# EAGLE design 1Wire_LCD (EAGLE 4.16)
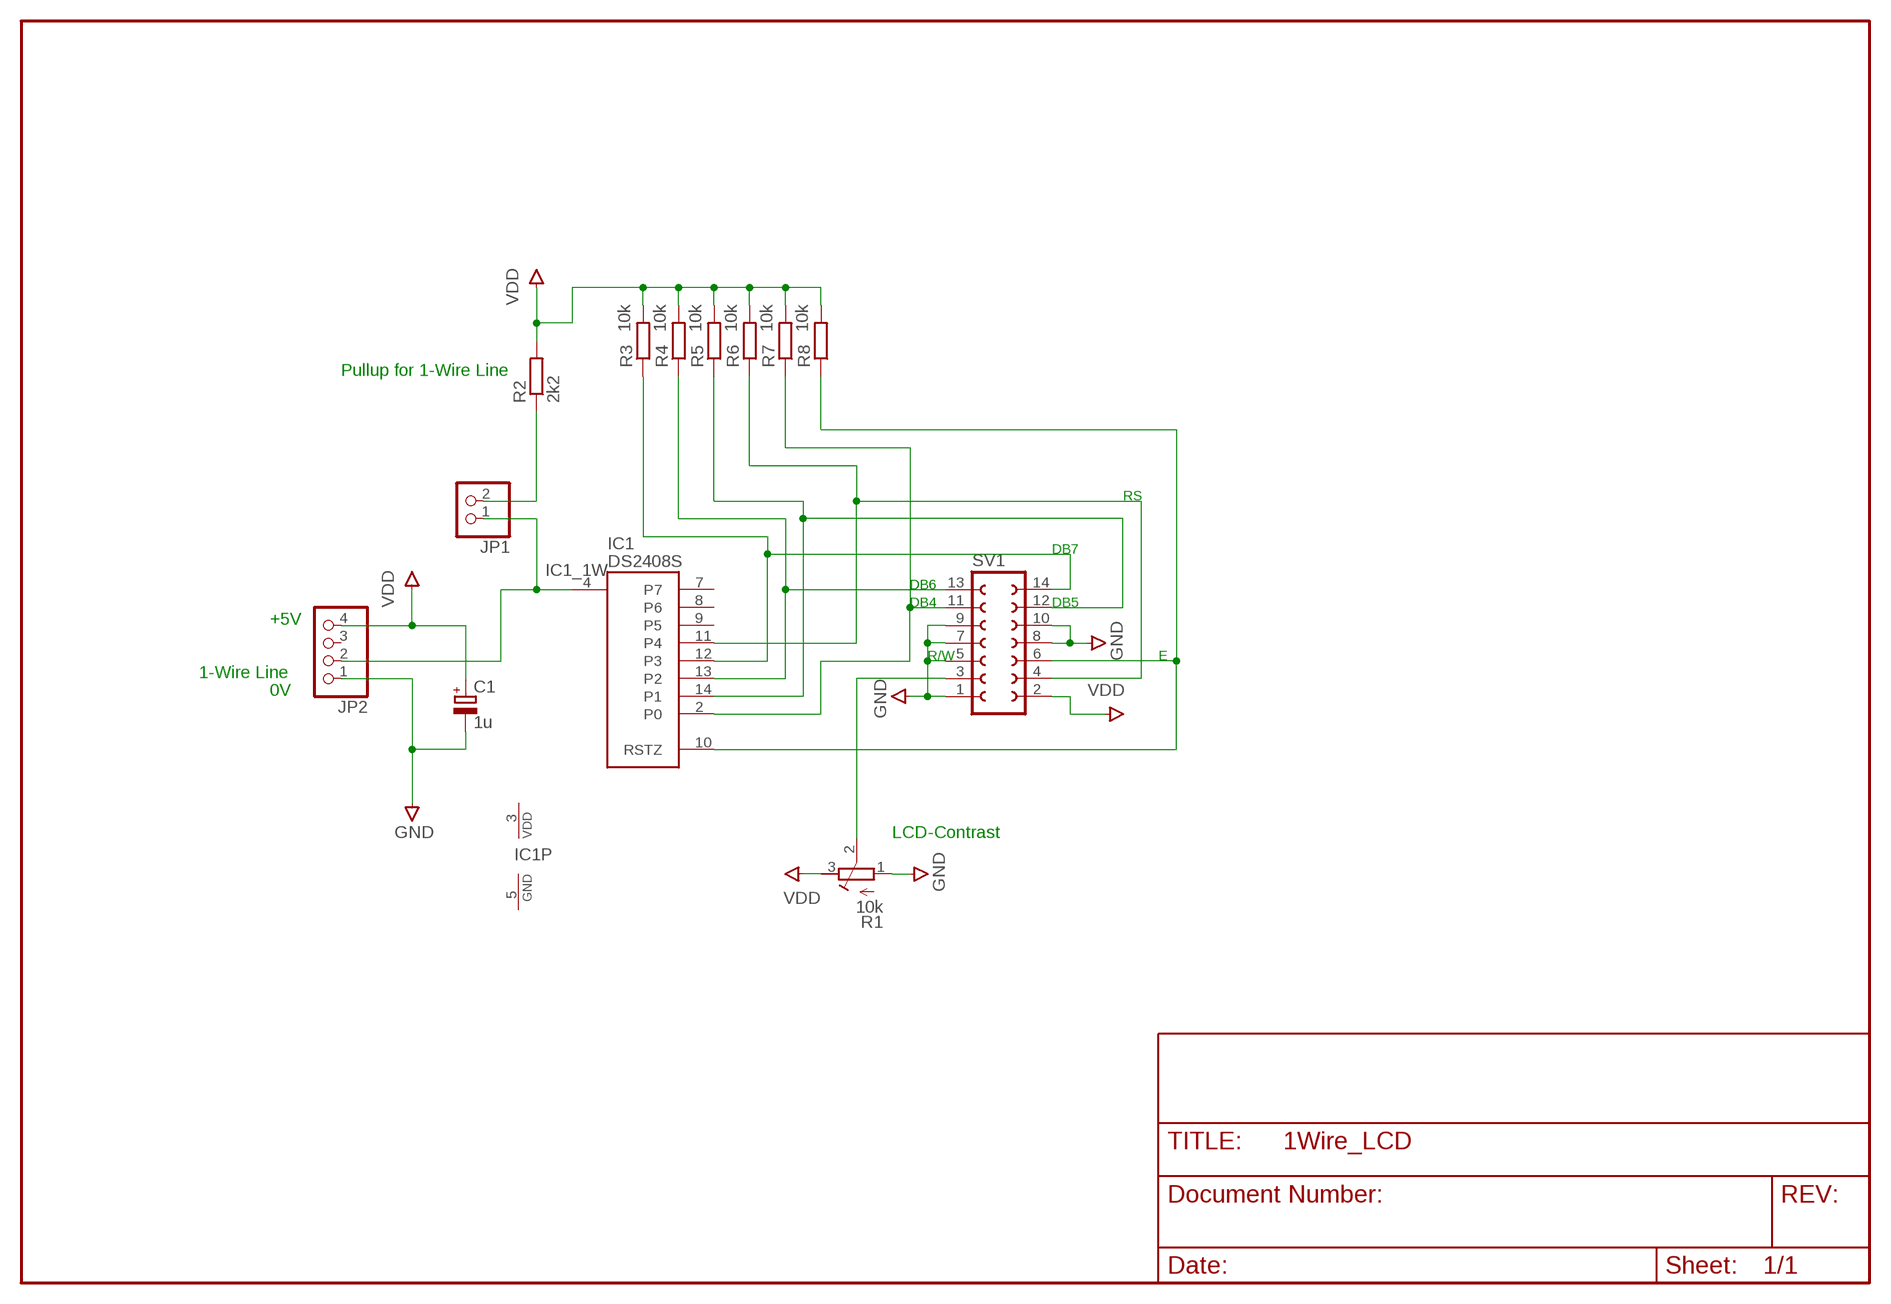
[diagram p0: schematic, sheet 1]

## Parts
C1  1u  CPOL-EUSMCP  [SMC_P]
IC1  DS2408S  [SO16]
JP1  PINHD-1X2  [1X02]
JP2  PINHD-1X4  [1X04]
R1  10k  R-TRIMM4G/J  [RTRIM4G/J]
R2  2k2  R-EU_M1206  [M1206]
R3  10k  R-EU_M1206  [M1206]
R4  10k  R-EU_M1206  [M1206]
R5  10k  R-EU_M1206  [M1206]
R6  10k  R-EU_M1206  [M1206]
R7  10k  R-EU_M1206  [M1206]
R8  10k  R-EU_M1206  [M1206]
SV1  FE07-2  [FE07-2]

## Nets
CONTRAST: R1.2(S) SV1.3
DB4: IC1.2(P0) R7.1 SV1.11
DB5: IC1.14(P1) R5.1 SV1.12
DB6: IC1.13(P2) R4.1 SV1.13
DB7: IC1.12(P3) R3.1 SV1.14
E: IC1.10(RSTZ) R8.1 SV1.6
GND: C1.- JP2.1 R1.1(E) SV1.1 SV1.5 SV1.7 SV1.8 SV1.9 SV1.10
I/O: IC1.4(1W) JP1.1 JP2.2
N$2: JP1.2 R2.1
RS: IC1.11(P4) R6.1 SV1.4
VDD: C1.+ JP2.4 R1.3(A) R2.2 R3.2 R4.2 R5.2 R6.2 R7.2 R8.2 SV1.2
Unconnected: IC1.7 IC1.8(P6) IC1.9(P5) JP2.3

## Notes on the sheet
- Pullup for 1-Wire Line
- RS
- DB7
- DB6
- DB4 | DB5
- +5V
- R/W | E
- 1-Wire Line
- 0V
- LCD-Contrast

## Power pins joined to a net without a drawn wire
GND: IC1.5(GND)
VDD: IC1.3(VDD)

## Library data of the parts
C1 = rcl:CPOL-EU: POLARIZED CAPACITOR, European symbol
IC1 = 1wire:DS2408: 8-Channel Addressable Switch This is a general purpose I/O multiplier. The PIO pins P0..P7 are inputs/open drain outputs and can be used in a mixed I/O fashion. Output sink capability is appr. 4mA. Each input state can be read but changing input signals additionally trigger the egde detector for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
JP1 = pinhead:PINHD-1X2: PIN HEADER
JP2 = pinhead:PINHD-1X4: PIN HEADER
R1 = rcl:R-TRIMM: Trimm resistor
R2-R8 = rcl:R-EU_: RESISTOR, European symbol
SV1 = con-lsta:FE07-2: FEMALE HEADER

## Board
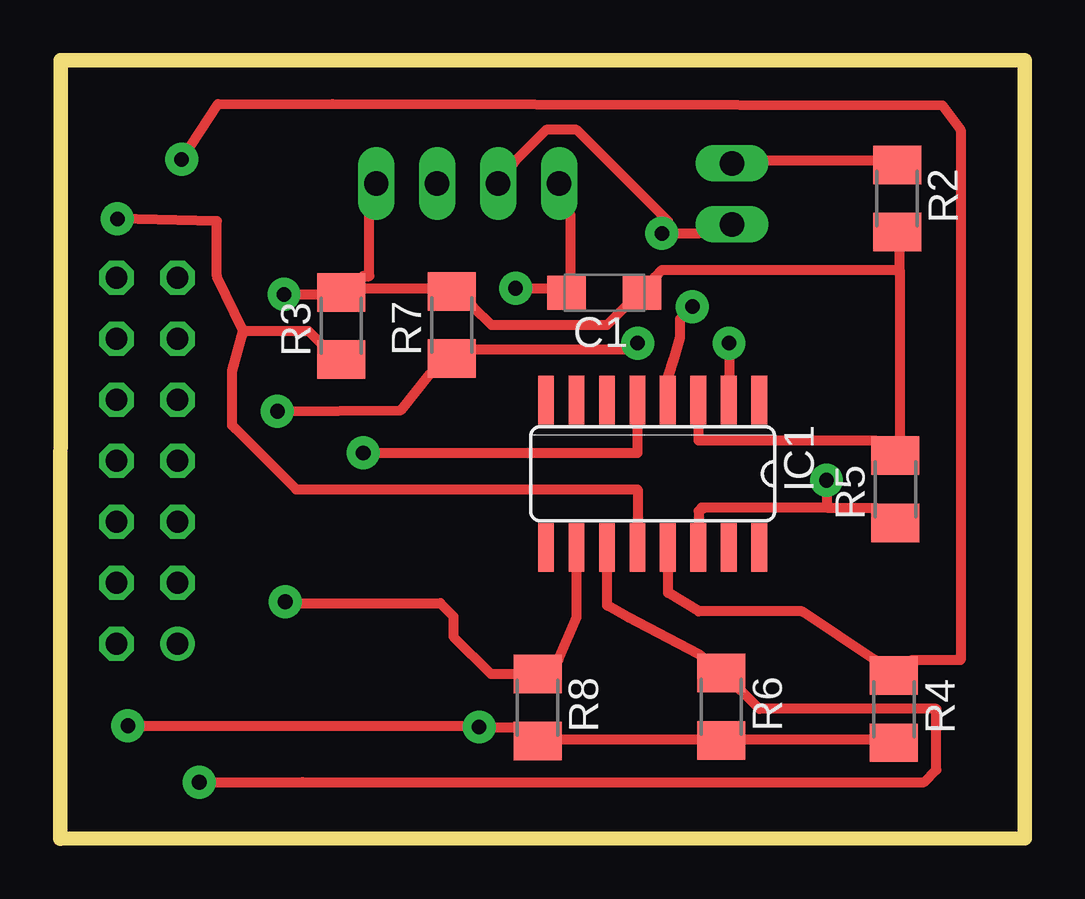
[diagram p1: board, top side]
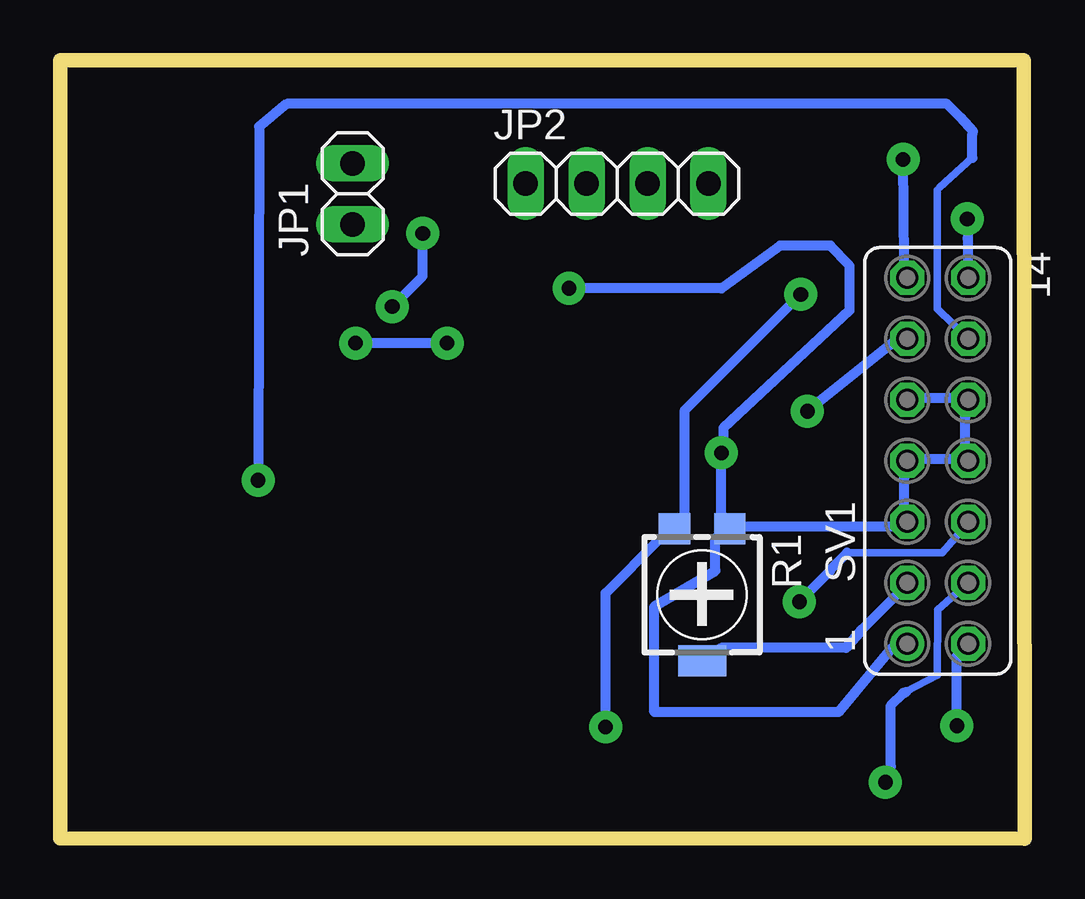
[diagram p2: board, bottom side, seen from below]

Size 40.2 x 32.45 mm. Coordinates in mm from the lower left corner, seen from the top.
Outline: 0,0 40.2,0.02 40.2,32.45 0.03,32.45 0,0
Copper layers (1*16): Top 0.035mm / dielectric 1.5mm / Bottom 0.035mm
Design rules "Doppelt_eigene": minimum track width 16mil, minimum drill 24mil, track to track 15mil, track to pad 15mil, pad to pad 20mil, via to via 20mil, smd to smd 8mil, copper to edge 40mil, drill to drill 8mil, minimum pad ring 10mil, minimum via ring 15mil, stop-mask expansion 4mil, vias tented up to drill 0mil, thermal gap 10mil
tRestrict: area 1.2,7.2 to 6.3,25
bRestrict: area 11.4,25 to 22.8,28.8; area 26.6,25 to 30.4,28.8

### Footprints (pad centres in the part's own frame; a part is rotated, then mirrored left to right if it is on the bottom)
SMC_P = smd 1.6 x 1.4: + -1.575,0; - 1.575,0
SO16 = smd 0.66 x 2.032: 1 -4.445,-3.073; 2 -3.175,-3.073; 3 -1.905,-3.073; 4 -0.635,-3.073; 5 0.635,-3.073; 6 1.905,-3.073; 7 3.175,-3.073; 8 4.445,-3.073; 9 4.445,3.073; 10 3.175,3.073; 11 1.905,3.073; 12 0.635,3.073; 13 -0.635,3.073; 14 -1.905,3.073; 15 -3.175,3.073; 16 -4.445,3.073
1X02 = drill 1.016 long: 1 -1.27,0; 2 1.27,0
1X04 = drill 1.016 long: 1 -3.81,0; 2 -1.27,0; 3 1.27,0; 4 3.81,0
RTRIM4G/J = smd 1.3 x 1.3: 1 -1.15,-2.75; 3 1.15,-2.75 | smd 2 x 1.3: 2 0,2.75
M1206 = smd 1.6 x 2: 1 -1.4,0; 2 1.4,0
FE07-2 = drill 0.914 round: 1 -7.62,1.27 | drill 0.914 octagon: 2 -7.62,-1.27; 3 -5.08,1.27; 4 -5.08,-1.27; 5 -2.54,1.27; 6 -2.54,-1.27; 7 0,1.27; 8 0,-1.27; 9 2.54,1.27; 10 2.54,-1.27; 11 5.08,1.27; 12 5.08,-1.27; 13 7.62,1.27; 14 7.62,-1.27

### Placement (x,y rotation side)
C1  22.68,22.75 180 top
IC1  24.7,15.21 180 top
JP1  28,26.87 90 bottom
JP2  16.98,27.3 0 bottom
R1  13.45,10.17 180 bottom
R2  34.88,26.67 270 top
R3  11.71,21.37 90 top
R4  34.75,5.4 270 top
R5  34.81,14.56 90 top
R6  27.55,5.5 270 top
R7  16.32,21.4 90 top
R8  19.9,5.46 270 top
SV1  3.62,15.75 90 bottom

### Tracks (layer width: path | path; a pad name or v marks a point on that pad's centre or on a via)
CONTRAST
  Bottom 0.406: R1.2 12.63,7.95 7.44,7.95 6.79,8.71 5.27,10.23 SV1.3
DB4  (via drill 0.61)
  Top 0.406: v9.06,17.81 14.21,17.86 15.43,19.38 R7.1 17.21,20.39 23.81,20.39 v24.07,20.65 | v27.88,20.65 27.88,19.25 IC1.2
  Bottom 0.406: v9.06,17.81 5.52,20.65 SV1.11 | v24.07,20.65 v27.88,20.65
DB5  (via drill 0.61)
  Top 0.406: 31.94,13.79 26.73,13.79 | 31.94,13.79 33.97,13.79 R5.1 | 26.61,13.66 26.61,13.03 IC1.14 | 26.73,13.79 26.61,13.66 | v31.94,14.93 31.94,13.79 | 31.94,13.79 26.73,13.79 | 26.73,13.79 26.86,13.79 26.61,13.66
  Bottom 0.305: SV1.12 3.64,22.08 3.65,27.02 3.54,27.14 2.18,28.36
  Bottom 0.406: v31.94,14.93 32.06,14.93 32.09,14.97 31.95,15.12 31.9,29.67 30.74,30.62 3.24,30.62 2.69,30.07 2.15,29.47 2.18,29.38 2.18,28.36
DB6  (via drill 0.61)
  Top 0.406: IC1.13 25.34,10.24 26.61,9.47 30.92,9.47 33.97,7.44 R4.1 35.49,7.44 37.53,7.44 37.53,29.54 36.77,30.55 11.35,30.62 6.58,30.6 v5.06,28.3
  Bottom 0.406: v5.06,28.3 5.02,23.95 SV1.13
DB7  (via drill 0.61 pad 0.81)
  Top 0.406: 7.62,21.16 10.35,21.16 10.86,20.65 R3.1 | 7.62,21.16 6.54,23.44 6.54,25.73 v2.39,25.83 | 24.07,13.15 IC1.12 24.07,13.15 | 7.62,21.16 7.17,19.51 7.17,17.22 7.3,17.09 9.84,14.55 24.07,14.55 24.07,13.15
  Bottom 0.406: v2.39,25.83 2.38,25.02 2.38,24 SV1.14
E  (via drill 0.61)
  Top 0.406: IC1.10 21.52,11 21.52,10.23 21.52,9.22 20.76,7.44 R8.1 17.95,6.86 16.39,8.42 16.39,9.27 15.84,9.82 9.5,9.82 v9.39,9.87
  Bottom 0.305: 2.35,13.16 3.44,11.92 7.39,11.92
  Bottom 0.406: 2.35,13.16 SV1.6 | 7.39,11.92 8.1,11.22 8.12,11.14 v9.39,9.87
GND  (via drill 0.61)
  Top 0.406: JP2.1 21.27,25.98 21.27,23.44 C1.- 20.51,22.93 v18.98,22.93 | v12.63,16.08 24.07,16.08 24.07,17.47 IC1.5
  Bottom 0.406: SV1.9 4.25,18.36 2.98,18.36 SV1.10 2.48,17.6 2.48,16.33 SV1.8 2.98,15.82 4.25,15.82 SV1.7 5.02,15.06 5.02,13.79 SV1.5 5.52,13.03 11.87,13.03 R1.1 | R1.1 12.63,13.54 v12.63,16.08 12.63,16.13 12.6,16.17 12.54,16.22 12.54,17.12 7.29,22.02 7.29,23.87 8.1,24.72 10.2,24.72 12.63,22.93 v18.98,22.93 | SV1.1 5.52,7.95 7.75,5.27 15.43,5.27 15.43,9.68 12.89,11.17 12.89,12.52 R1.1
I/O  (via drill 0.61)
  Top 0.406: v26.35,22.17 25.84,21.66 25.84,20.9 25.59,20.01 25.34,19.25 IC1.4 | JP1.1 26.61,25.22 v25.08,25.22 25.34,25.73 21.52,29.54 20.25,29.54 18.98,28.27 JP2.2
  Bottom 0.406: v26.35,22.17 25.08,23.44 v25.08,25.22
N$2
  Top 0.406: R2.1 33.97,28.27 29.4,28.27 JP1.2
RS  (via drill 0.61)
  Top 0.406: IC1.11 22.8,11 22.8,10.49 22.8,9.73 23.68,9.22 26.61,7.69 R6.1 28.38,6.17 29.14,5.41 36.51,5.41 36.51,2.87 36,2.36 10.1,2.36 v5.8,2.35
  Bottom 0.305: 4.95,6.12 3.65,6.82 3.62,9.53 SV1.4
  Bottom 0.406: 5.07,6.06 4.95,6.12 5.07,6.06 | 5.07,6.06 5.58,5.55 5.58,3.01 v5.8,2.35
VDD  (via drill 0.61)
  Top 0.406: R3.2 12.63,22.93 15.43,22.93 R7.2 17.21,22.17 17.97,21.41 22.8,21.41 23.56,22.17 C1.+ 24.83,23.44 25.08,23.7 34.99,23.7 | JP2.4 12.89,25.98 12.89,23.44 12.63,23.44 R3.2 | 34.99,23.7 34.99,24.71 R2.2 | 34.99,23.7 34.99,16.58 R5.2 33.97,16.58 26.61,16.58 26.61,17.22 IC1.3 | R4.2 33.97,4.14 28.38,4.14 R6.2 26.61,4.14 20.76,4.14 R8.2 18.98,4.65 17.97,4.65 v17.46,4.65 16.95,4.7 v2.83,4.7 | v9.33,22.68 10.86,22.68 R3.2
  Bottom 0.406: v17.46,4.65 17.46,10.23 15.18,12.52 R1.3 14.16,13.54 14.16,17.85 v9.33,22.68 | v2.83,4.7 2.83,7.6 SV1.2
